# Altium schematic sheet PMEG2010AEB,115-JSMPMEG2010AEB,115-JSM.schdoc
size 127 x 101 mm
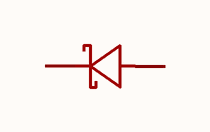
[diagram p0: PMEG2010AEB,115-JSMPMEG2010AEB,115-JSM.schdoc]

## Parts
D?  pmeg2010aeb,115-jsm  [SOD-523_L1.2-W0.8-LS1.6-RD-2]  (value not drawn)

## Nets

Not connected (* = marked no-connect by the designer): D? 1(C) 2(A)

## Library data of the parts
D? = pmeg2010aeb,115-jsm: 二极管配置:1个独立式;正向压降(Vf):370mV@20mA；600mV@200mA;直流反向耐压(Vr):40V;整流电流:350mA;; Manufacturer: JSMSEMI(杰盛微); AddInBom: yes; ModelId: a6fcdc3447de4b4888d5e65d03861b6b; ModelTransform: 62.992,31.496,0,0,0,0,0,0,0; Diode Configuration: 1个独立式; Voltage - DC Reverse(Vr): 40V; Current - Rectified: 350mA; Reverse Leakage Current (Ir): 5uA@30V; Operating Junction Temperature Range: -65℃~+125℃; Non-Repetitive Peak Forward Surge Current: 1.5A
